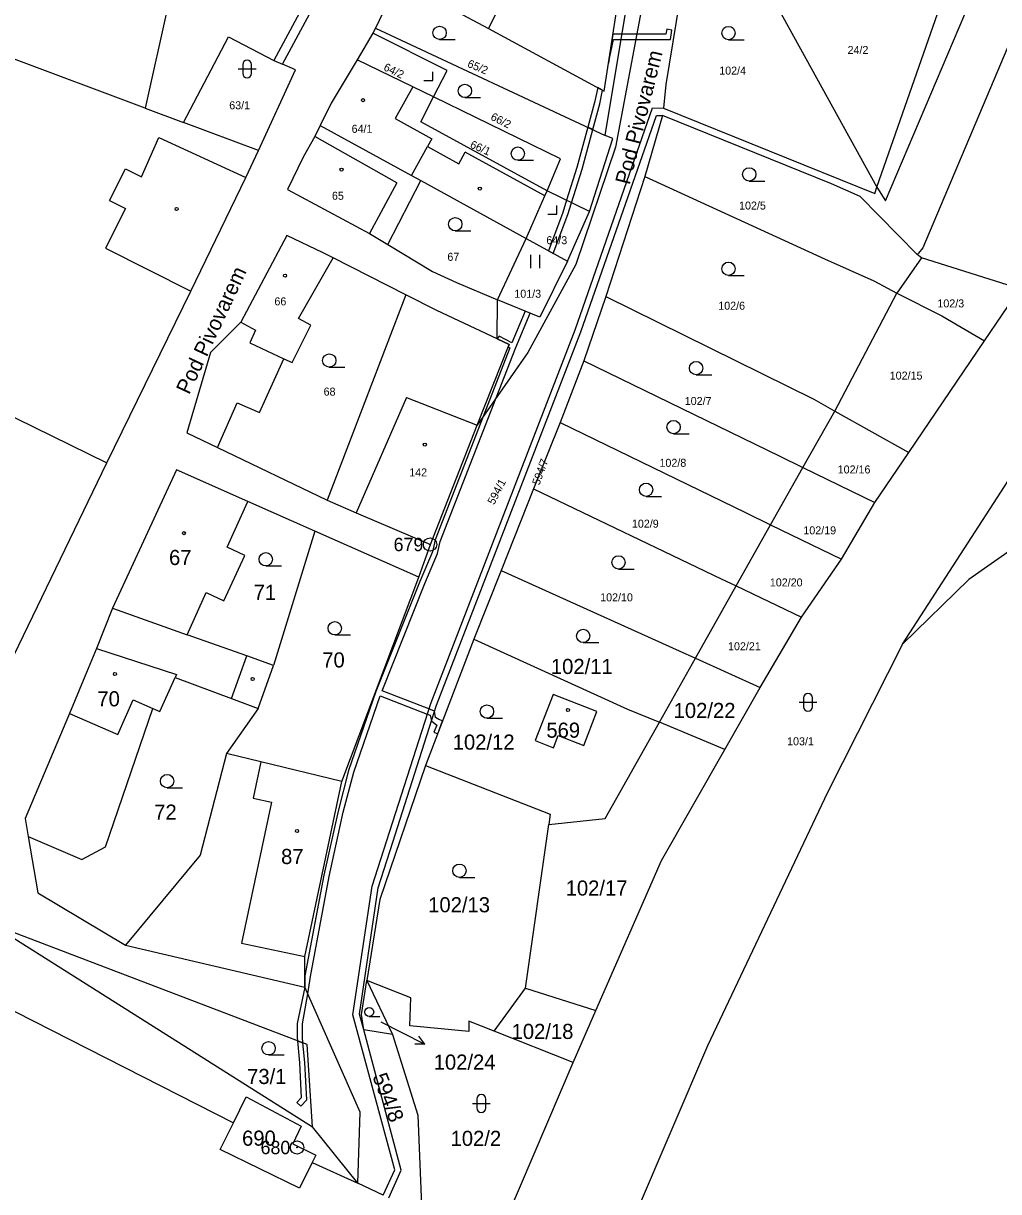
# Model space of a CAD drawing. Extents: x -758582 to -751794, y -998770 to -994350.
# Drawn here: x -755599.9 to -755490.3, y -995947.8 to -995816.3 of the extents above; entities that cross this region are included whole.
import ezdxf

# ---------------------------------------------------------------- set-up
doc = ezdxf.new("R2010")
doc.units = 0
for name, color, linetype in [('Hranice parcel', 7, 'Continuous'), ('Parcelní čísla', 7, 'Continuous'), ('Pop  PČ popisy', 7, 'Continuous'), ('Vnitřní kresba', 7, 'Continuous'), ('Věcná břemena k části', 7, 'Continuous'), ('Značky bodu BP', 7, 'Continuous'), ('Značky budov', 7, 'Continuous'), ('Značky kultur', 7, 'Continuous')]:
    doc.layers.add(name, color=color, linetype=linetype)

msp = doc.modelspace()

# ---------------------------------------------------------------- linework, layer by layer
at = {"layer": 'Hranice parcel'}
for p, q in [((-755520.42, -995804.92), (-755503.98, -995834.78)), ((-755557.34, -995810.55), (-755560.36, -995816.89)), ((-755551.75, -995814.75), (-755547.65, -995816.93)), ((-755560.66, -995817.44), (-755562.4, -995820.43)), ((-755560.36, -995816.89), (-755560.66, -995817.44)), ((-755560.36, -995816.89), (-755534.52, -995828.96)), ((-755571.79, -995820.54), (-755570.82, -995820.95)), ((-755586.26, -995825.88), (-755581.94, -995827.5)), ((-755528.07, -995826.7), (-755530.08, -995833.58)), ((-755529.19, -995825.85), (-755527.98, -995825.87)), ((-755528.77, -995826.71), (-755528.07, -995826.7)), ((-755573.52, -995830.66), (-755581.94, -995827.5)), ((-755558.98, -995841.21), (-755555.27, -995834.01)), ((-755555.27, -995834.01), (-755543.43, -995840.56)), ((-755530.08, -995833.58), (-755534.47, -995847.08)), ((-755536.3, -995837.52), (-755541.05, -995835.17)), ((-755538.76, -995843.08), (-755536.3, -995837.52)), ((-755546.64, -995847.43), (-755543.43, -995840.56)), ((-755543.43, -995840.56), (-755538.76, -995843.08)), ((-755499.31, -995842.18), (-755499.45, -995842.33)), ((-755498.96, -995842.74), (-755499.45, -995842.33)), ((-755556.96, -995846.87), (-755565.12, -995842.73)), ((-755498.96, -995842.74), (-755501.74, -995846.69)), ((-755487.9, -995846.2), (-755498.96, -995842.74)), ((-755491.86, -995852.05), (-755487.9, -995846.2)), ((-755556.96, -995846.87), (-755565.79, -995870)), ((-755546.68, -995851.83), (-755546.64, -995847.43)), ((-755534.47, -995847.08), (-755536.91, -995854.3)), ((-755534.47, -995847.08), (-755511.07, -995858.64)), ((-755508.72, -995859.96), (-755501.74, -995846.69)), ((-755569.72, -995854.51), (-755567.61, -995850.3)), ((-755500.39, -995864.64), (-755491.86, -995852.05)), ((-755536.91, -995854.3), (-755539.59, -995861.23)), ((-755536.91, -995854.3), (-755514.98, -995864.99)), ((-755511.07, -995858.64), (-755508.72, -995859.96)), ((-755512.29, -995866.3), (-755508.72, -995859.96)), ((-755508.72, -995859.96), (-755500.39, -995864.64)), ((-755554.16, -995874.97), (-755548.93, -995861.53)), ((-755539.59, -995861.23), (-755542.59, -995868.7)), ((-755539.59, -995861.23), (-755518.75, -995871.38)), ((-755578.13, -995864.06), (-755565.79, -995870)), ((-755514.98, -995864.99), (-755512.29, -995866.3)), ((-755504.19, -995870.25), (-755500.39, -995864.64)), ((-755515.92, -995872.76), (-755512.29, -995866.3)), ((-755512.29, -995866.3), (-755504.19, -995870.25)), ((-755542.59, -995868.7), (-755546.21, -995877.89)), ((-755542.59, -995868.7), (-755521.48, -995878.82)), ((-755567.18, -995873.47), (-755574.71, -995870.14)), ((-755507.96, -995876.63), (-755504.19, -995870.25)), ((-755518.75, -995871.38), (-755515.92, -995872.76)), ((-755519.79, -995879.63), (-755515.92, -995872.76)), ((-755515.92, -995872.76), (-755507.96, -995876.63)), ((-755567.18, -995873.47), (-755571.82, -995888.57)), ((-755555.47, -995878.66), (-755567.18, -995873.47)), ((-755555.47, -995878.66), (-755554.16, -995874.97)), ((-755512.46, -995883.14), (-755507.96, -995876.63)), ((-755546.21, -995877.89), (-755549.31, -995885.63)), ((-755546.21, -995877.89), (-755526.21, -995886.93)), ((-755564.14, -995901.65), (-755555.47, -995878.66)), ((-755521.48, -995878.82), (-755519.79, -995879.63)), ((-755524.37, -995887.76), (-755519.79, -995879.63)), ((-755519.79, -995879.63), (-755512.46, -995883.14)), ((-755517.1, -995891.05), (-755512.46, -995883.14)), ((-755549.31, -995885.63), (-755554.72, -995899.85)), ((-755549.31, -995885.63), (-755532.01, -995893.48)), ((-755591.72, -995886.67), (-755582.73, -995889.61)), ((-755526.21, -995886.93), (-755524.37, -995887.76)), ((-755573.55, -995893.44), (-755571.82, -995888.57)), ((-755528.42, -995894.96), (-755524.37, -995887.76)), ((-755524.37, -995887.76), (-755517.1, -995891.05)), ((-755584.59, -995893.75), (-755582.89, -995889.92)), ((-755582.73, -995889.61), (-755582.89, -995889.92)), ((-755521.08, -995898.04), (-755517.1, -995891.05)), ((-755573.55, -995893.44), (-755577.11, -995898.48)), ((-755532.01, -995893.48), (-755528.42, -995894.96)), ((-755521.08, -995898.04), (-755528.42, -995894.96)), ((-755554.72, -995899.85), (-755559.85, -995914.9)), ((-755554.72, -995899.85), (-755540.71, -995905.32)), ((-755540.71, -995905.32), (-755540.85, -995906.46)), ((-755543.5, -995924.88), (-755540.85, -995906.46)), ((-755559.85, -995914.9), (-755561.32, -995924.01)), ((-755603.54, -995917.67), (-755567.43, -995940.49)), ((-755588.45, -995920.03), (-755568.31, -995924.79)), ((-755561.32, -995924.01), (-755558.43, -995930.08)), ((-755547, -995929.71), (-755543.5, -995924.88)), ((-755543.5, -995924.88), (-755535.57, -995927.39)), ((-755561.67, -995929.57), (-755562.16, -995927.82)), ((-755538.13, -995933.24), (-755535.57, -995927.39)), ((-755558.43, -995930.08), (-755561.67, -995929.57)), ((-755538.13, -995933.24), (-755547, -995929.71)), ((-755547.06, -995954.19), (-755538.13, -995933.24)), ((-755562.35, -995946.84), (-755567.43, -995940.49)), ((-755567.49, -995944.51), (-755562.35, -995946.84)), ((-755559.5, -995948.19), (-755558.18, -995945.32)), ((-755559.5, -995948.19), (-755562.35, -995946.84))]:
    msp.add_line(p, q, dxfattribs=at)
for points in [[(-755489.32, -995719.48), (-755477.02, -995766.71), (-755484.53, -995807.78), (-755498.8, -995841.6), (-755499.31, -995842.18)], [(-755538.17, -995789.33), (-755529.99, -995802.59), (-755529.67, -995810.51), (-755533.37, -995830.29), (-755537.81, -995843.47), (-755543.24, -995853.38), (-755548.93, -995861.53)], [(-755570.82, -995820.95), (-755564.91, -995809.98), (-755557.18, -995795.28)], [(-755503.98, -995834.78), (-755493.46, -995804.64), (-755491.49, -995794.37)], [(-755503.98, -995834.78), (-755503.02, -995836.3), (-755490.26, -995806.26), (-755487.94, -995794.93)], [(-755582.21, -995803.41), (-755567.05, -995811.71), (-755571.79, -995820.54)], [(-755547.65, -995816.93), (-755542.35, -995806.35), (-755539.54, -995806.3)], [(-755523.79, -995806.25), (-755525, -995806.73), (-755527.7, -995823.23), (-755527.98, -995825.87)], [(-755584.98, -995808.56), (-755587.07, -995812.46), (-755583.66, -995814.26), (-755586.26, -995825.88)], [(-755547.65, -995816.93), (-755534.64, -995823.96), (-755532.34, -995809.15)], [(-755534.52, -995828.96), (-755531.3, -995809.54), (-755532.34, -995809.15)], [(-755553.82, -995824.62), (-755552.3, -995821.66), (-755560.66, -995817.44)], [(-755586.26, -995825.88), (-755601.67, -995820.12), (-755610.61, -995818.09)], [(-755581.94, -995827.5), (-755576.87, -995817.85), (-755571.79, -995820.54)], [(-755573.52, -995830.66), (-755569.34, -995821.56), (-755570.82, -995820.95)], [(-755562.4, -995820.43), (-755565.33, -995825.31), (-755566.57, -995827.82)], [(-755553.82, -995824.62), (-755556.15, -995823.48), (-755562.4, -995820.43)], [(-755541.05, -995835.17), (-755555.26, -995827.41), (-755553.82, -995824.62)], [(-755541.05, -995835.17), (-755539.55, -995831.6), (-755553.82, -995824.62)], [(-755558.18, -995945.32), (-755562.9, -995927.88), (-755560.74, -995913.41), (-755554.15, -995892.86), (-755537.92, -995850.84), (-755529.19, -995825.85)], [(-755562.16, -995927.82), (-755560.06, -995913.61), (-755558.4, -995908.45), (-755553.5, -995893.06), (-755537.27, -995851.05), (-755528.77, -995826.71)], [(-755499.45, -995842.33), (-755505.84, -995835.82), (-755509.06, -995834.39), (-755528.07, -995826.7)], [(-755527.98, -995825.87), (-755504.22, -995835.48), (-755503.98, -995834.78)], [(-755566.57, -995827.82), (-755567.19, -995829.08), (-755568.5, -995831.4), (-755570.25, -995835.02), (-755561.01, -995839.97), (-755558.98, -995841.21)], [(-755566.57, -995827.82), (-755556.29, -995833.45), (-755555.27, -995834.01)], [(-755536.3, -995837.52), (-755533.66, -995829.3), (-755534.52, -995828.96)], [(-755618.51, -995909.9), (-755611.25, -995908.1), (-755600.46, -995886.3), (-755590.57, -995865.79), (-755581.11, -995846.48), (-755574.92, -995833.7), (-755573.52, -995830.66)], [(-755530.08, -995833.58), (-755509.86, -995842.82), (-755504.3, -995845.3), (-755501.74, -995846.69)], [(-755543.43, -995840.56), (-755541.31, -995835.76), (-755541.05, -995835.17)], [(-755565.12, -995842.73), (-755566.22, -995842.16), (-755570.33, -995840.2), (-755575.51, -995849.96), (-755578.89, -995853.37), (-755581.56, -995862.41), (-755578.13, -995864.06)], [(-755558.98, -995841.21), (-755553.94, -995844.27), (-755551.24, -995845.51), (-755546.64, -995847.43)], [(-755567.61, -995850.3), (-755569.03, -995849.55), (-755565.12, -995842.73)], [(-755538.76, -995843.08), (-755541.89, -995849.4), (-755546.64, -995847.43)], [(-755546.68, -995851.83), (-755553.46, -995848.64), (-755556.96, -995846.87)], [(-755501.74, -995846.69), (-755496.68, -995849.23), (-755491.86, -995852.05)], [(-755501.09, -995886.17), (-755485.59, -995862.19), (-755476.21, -995849.9)], [(-755548.93, -995861.53), (-755545.32, -995852.47), (-755546.68, -995851.83)], [(-755472.53, -995851.07), (-755474.46, -995862.26), (-755475.15, -995865.92), (-755485.34, -995873.1), (-755493.64, -995878.9), (-755501.09, -995886.17)], [(-755578.13, -995864.06), (-755575.92, -995859.04), (-755573.4, -995860.13), (-755570.66, -995854.08), (-755569.72, -995854.51)], [(-755574.71, -995870.14), (-755582.72, -995866.59), (-755589.94, -995882.15), (-755591.72, -995886.67)], [(-755571.82, -995888.57), (-755574.84, -995887.51), (-755581.53, -995885.14), (-755579.39, -995880.37), (-755577.39, -995881.3), (-755575.04, -995876.22), (-755577.05, -995875.28), (-755574.71, -995870.14)], [(-755565.79, -995870), (-755562.53, -995871.42), (-755554.16, -995874.97)], [(-755591.72, -995886.67), (-755593.04, -995889.82), (-755594.78, -995893.97), (-755599.74, -995905.79), (-755599.4, -995907.81)], [(-755501.09, -995886.17), (-755509.51, -995902.87), (-755523.02, -995931.37), (-755531.04, -995950.11), (-755530.43, -995962.15)], [(-755582.89, -995889.92), (-755576.54, -995892.29), (-755573.55, -995893.44)], [(-755542.4, -995897.04), (-755540.34, -995897.84), (-755539.81, -995896.46), (-755536.94, -995897.57), (-755535.46, -995893.76), (-755540.39, -995891.85), (-755542.4, -995897.04)], [(-755599.4, -995907.81), (-755593.38, -995910.41), (-755590.71, -995908.98), (-755585.38, -995893.41), (-755584.59, -995893.75)], [(-755540.85, -995906.46), (-755534.52, -995905.8), (-755528.42, -995894.96)], [(-755577.11, -995898.48), (-755580.07, -995909.93), (-755588.45, -995920.03)], [(-755564.14, -995901.65), (-755573.25, -995899.42), (-755577.11, -995898.48)], [(-755535.57, -995927.39), (-755528.18, -995910.52), (-755521.08, -995898.04)], [(-755568.31, -995924.79), (-755568.31, -995921.34), (-755564.14, -995901.65)], [(-755599.4, -995907.81), (-755598.31, -995914.17), (-755588.45, -995920.03)], [(-755567.43, -995940.49), (-755568.03, -995931.24), (-755603.54, -995917.67)], [(-755615.6, -995919.2), (-755607.06, -995924.41), (-755576.33, -995940.02)], [(-755561.67, -995929.57), (-755561.94, -995927.83), (-755561.32, -995924.01)], [(-755547, -995929.71), (-755549.85, -995928.58), (-755549.87, -995929.77), (-755556.5, -995929.11), (-755556.38, -995925.98), (-755561.32, -995924.01)], [(-755562.35, -995946.84), (-755562.06, -995938.82), (-755568.31, -995924.79)], [(-755558.87, -995948.48), (-755557.45, -995945.37), (-755561.67, -995929.57)], [(-755558.43, -995930.08), (-755555.61, -995939.19), (-755555.16, -995950.24)], [(-755576.33, -995940.02), (-755574.91, -995937.11), (-755568.73, -995940.41), (-755569.65, -995942.41), (-755567.08, -995943.67), (-755567.49, -995944.51)], [(-755567.49, -995944.51), (-755568.9, -995947.39), (-755577.81, -995943.04), (-755576.33, -995940.02)]]:
    msp.add_lwpolyline(points, dxfattribs=at)
at = {"layer": 'Pop  PČ popisy'}
for p, q in [((-755559.74, -995928.67), (-755557.48, -995929.83)), ((-755557.48, -995929.83), (-755554.81, -995931.19)), ((-755554.81, -995931.19), (-755555.47, -995930.29)), ((-755554.81, -995931.19), (-755555.93, -995931.18))]:
    msp.add_line(p, q, dxfattribs=at)
at = {"layer": 'Vnitřní kresba'}
for p, q in [((-755556.15, -995823.48), (-755558.13, -995827.06)), ((-755558.13, -995827.06), (-755554.01, -995829.34)), ((-755586.67, -995833.6), (-755584.71, -995829.19)), ((-755584.71, -995829.19), (-755574.92, -995833.7)), ((-755557.96, -995834.29), (-755567.19, -995829.08)), ((-755554.01, -995829.34), (-755554.5, -995830.21)), ((-755556.29, -995833.45), (-755554.5, -995830.21)), ((-755554.5, -995830.21), (-755551, -995832.15)), ((-755551, -995832.15), (-755550.27, -995830.83)), ((-755541.31, -995835.76), (-755550.27, -995830.83)), ((-755590.26, -995836.27), (-755588.46, -995832.7)), ((-755588.46, -995832.7), (-755586.67, -995833.6)), ((-755557.96, -995834.29), (-755561.01, -995839.97)), ((-755588.47, -995837.17), (-755590.72, -995841.64)), ((-755590.26, -995836.27), (-755588.47, -995837.17)), ((-755590.72, -995841.64), (-755581.11, -995846.48)), ((-755575.51, -995849.96), (-755573.83, -995850.85)), ((-755573.83, -995850.85), (-755574.5, -995852.3)), ((-755574.5, -995852.3), (-755570.66, -995854.08)), ((-755609.7, -995856.42), (-755590.57, -995865.79)), ((-755556.87, -995858.43), (-755562.53, -995871.42)), ((-755556.87, -995858.43), (-755548.93, -995861.53)), ((-755589.94, -995882.15), (-755581.53, -995885.14)), ((-755576.54, -995892.29), (-755574.84, -995887.51)), ((-755589.31, -995896.34), (-755587.62, -995892.44)), ((-755587.62, -995892.44), (-755585.38, -995893.41)), ((-755594.78, -995893.97), (-755589.31, -995896.34)), ((-755573.25, -995899.42), (-755574.12, -995903.51)), ((-755572.05, -995903.95), (-755575.41, -995919.84)), ((-755574.12, -995903.51), (-755572.05, -995903.95)), ((-755575.41, -995919.84), (-755568.31, -995921.34))]:
    msp.add_line(p, q, dxfattribs=at)
at = {"layer": 'Věcná břemena k části'}
for points in [[(-755527.61, -995817.01), (-755527.7, -995817.57), (-755530.99, -995817.57), (-755532.63, -995817.56), (-755533.65, -995817.56), (-755534.16, -995820.84), (-755533.58, -995818.16), (-755532.73, -995818.16), (-755531.1, -995818.16), (-755527.18, -995818.17), (-755527.02, -995817.1)], [(-755535.36, -995823.57), (-755535.72, -995825.24), (-755536.48, -995828.04), (-755535.93, -995828.3), (-755535.14, -995825.38), (-755534.81, -995823.87)], [(-755540.36, -995842.22), (-755538.73, -995837.83), (-755538.32, -995836.52), (-755537.13, -995832.73), (-755535.93, -995828.3), (-755536.48, -995828.04), (-755537.71, -995832.57), (-755538.86, -995836.25), (-755539.29, -995837.63), (-755540.9, -995841.93)], [(-755542.97, -995848.95), (-755543.53, -995848.72), (-755545.02, -995852.28), (-755546.44, -995851.55), (-755546.68, -995851.83), (-755545.32, -995852.47), (-755545.43, -995852.74), (-755545.25, -995852.83), (-755548.25, -995860.56), (-755553.65, -995874.46), (-755553.95, -995875.81), (-755555.38, -995879.15), (-755560.32, -995891.51), (-755563.38, -995900.39), (-755564.57, -995904.96), (-755566.16, -995912.19), (-755568.31, -995923.48), (-755568.31, -995924.79), (-755569.15, -995928.85), (-755569.18, -995930.43), (-755569.14, -995930.81), (-755568.52, -995931.05), (-755568.58, -995930.41), (-755568.55, -995928.91), (-755567.98, -995925.53), (-755567.65, -995923.58), (-755565.58, -995912.31), (-755563.99, -995905.1), (-755562.8, -995900.57), (-755559.83, -995892.01), (-755554.53, -995894.05), (-755554.21, -995894.17), (-755554.06, -995894.82), (-755553.47, -995895.3), (-755553.78, -995896.1), (-755553.35, -995896.26), (-755552.81, -995894.82), (-755553.23, -995894.66), (-755553.6, -995894.42), (-755553.71, -995893.72), (-755554.35, -995893.47), (-755559.62, -995891.45), (-755554.82, -995879.37), (-755553.37, -995875.99), (-755553.07, -995874.64), (-755546.79, -995858.46), (-755544.59, -995852.8)], [(-755568.52, -995931.05), (-755569.14, -995930.81), (-755568.91, -995933.29), (-755568.71, -995937.24), (-755569.19, -995937.75), (-755568.76, -995938.16), (-755568.09, -995937.46), (-755568.31, -995933.25)]]:
    msp.add_lwpolyline(points, close=True, dxfattribs=at)
at = {"layer": 'Značky bodu BP'}
for centre, radius in [((-755554.22, -995874.97), 0.75), ((-755554.22, -995874.97), 0.03), ((-755569.18, -995942.81), 0.75), ((-755569.18, -995942.81), 0.03)]:
    msp.add_circle(centre, radius, dxfattribs=at)
at = {"layer": 'Značky budov'}
for centre in [(-755561.77, -995824.98), (-755564.18, -995832.8), (-755548.62, -995834.94), (-755582.72, -995837.23), (-755570.53, -995844.73), (-755554.8, -995863.73), (-755581.9, -995873.7), (-755589.65, -995889.55), (-755574.17, -995890.1), (-755538.71, -995893.59), (-755569.18, -995907.21)]:
    msp.add_circle(centre, 0.175, dxfattribs=at)
at = {"layer": 'Značky kultur'}
for p, q in [((-755553.14, -995818.16), (-755551.39, -995818.16)), ((-755520.66, -995818.18), (-755518.91, -995818.18)), ((-755575.79, -995821.47), (-755573.79, -995821.47)), ((-755575.29, -995820.97), (-755575.29, -995821.97)), ((-755574.29, -995821.97), (-755574.29, -995820.97)), ((-755554.92, -995822.78), (-755553.92, -995822.78)), ((-755553.92, -995822.78), (-755553.92, -995821.78)), ((-755550.3, -995824.69), (-755548.55, -995824.69)), ((-755544.35, -995831.75), (-755542.6, -995831.75)), ((-755518.33, -995834.08), (-755516.58, -995834.08)), ((-755539.96, -995837.82), (-755539.96, -995836.82)), ((-755540.96, -995837.82), (-755539.96, -995837.82)), ((-755551.38, -995839.69), (-755549.63, -995839.69)), ((-755542.87, -995843.87), (-755542.87, -995842.37)), ((-755541.87, -995843.87), (-755541.87, -995842.37)), ((-755520.66, -995844.7), (-755518.91, -995844.7)), ((-755565.55, -995855.02), (-755563.8, -995855.02)), ((-755524.3, -995855.88), (-755522.55, -995855.88)), ((-755526.84, -995862.51), (-755525.09, -995862.51)), ((-755529.93, -995869.56), (-755528.18, -995869.56)), ((-755572.69, -995877.39), (-755570.94, -995877.39)), ((-755533.03, -995877.73), (-755531.28, -995877.73)), ((-755564.93, -995885.15), (-755563.18, -995885.15)), ((-755537, -995886.01), (-755535.25, -995886.01)), ((-755512.22, -995892.22), (-755512.22, -995893.22)), ((-755511.22, -995893.22), (-755511.22, -995892.22)), ((-755512.72, -995892.72), (-755510.72, -995892.72)), ((-755547.82, -995894.52), (-755546.07, -995894.52)), ((-755583.79, -995902.34), (-755582.04, -995902.34)), ((-755550.92, -995912.42), (-755549.17, -995912.42)), ((-755561.06, -995928.06), (-755559.88, -995928.06)), ((-755572.37, -995932.4), (-755570.62, -995932.4)), ((-755549.46, -995937.86), (-755547.46, -995937.86)), ((-755548.96, -995937.36), (-755548.96, -995938.36)), ((-755547.96, -995938.36), (-755547.96, -995937.36))]:
    msp.add_line(p, q, dxfattribs=at)
for centre, radius in [((-755553.14, -995817.41), 0.75), ((-755520.66, -995817.43), 0.75), ((-755550.3, -995823.94), 0.75), ((-755544.35, -995831), 0.75), ((-755518.33, -995833.33), 0.75), ((-755551.38, -995838.94), 0.75), ((-755520.66, -995843.95), 0.75), ((-755565.55, -995854.27), 0.75), ((-755524.3, -995855.13), 0.75), ((-755526.84, -995861.76), 0.75), ((-755529.93, -995868.81), 0.75), ((-755572.69, -995876.64), 0.75), ((-755533.03, -995876.98), 0.75), ((-755564.93, -995884.4), 0.75), ((-755537, -995885.26), 0.75), ((-755547.82, -995893.77), 0.75), ((-755583.79, -995901.59), 0.75), ((-755550.92, -995911.67), 0.75), ((-755561.06, -995927.56), 0.502), ((-755572.37, -995931.65), 0.75)]:
    msp.add_circle(centre, radius, dxfattribs=at)
for centre, start, end in [((-755574.79, -995820.97), 0, 180), ((-755574.79, -995821.97), 180, 359.9879), ((-755511.72, -995892.22), 0, 180), ((-755511.72, -995893.22), 180, 359.9879), ((-755548.46, -995937.36), 0, 180), ((-755548.46, -995938.36), 180, 359.9879)]:
    msp.add_arc(centre, 0.5, start, end, dxfattribs=at)

# ---------------------------------------------------------------- texts
at = {"layer": 'Parcelní čísla'}
for s, height, p in [('24/2', 0.9, (-755507.27, -995819.79)), ('102/4', 0.9, (-755521.7, -995822.11)), ('63/1', 0.9, (-755576.8, -995826.01)), ('64/1', 0.9, (-755563.04, -995828.66)), ('65', 0.9, (-755565.25, -995836.19)), ('102/5', 0.9, (-755519.47, -995837.29)), ('64/3', 0.9, (-755541.14, -995841.19)), ('67', 0.9, (-755552.27, -995843.06)), ('101/3', 0.9, (-755544.74, -995847.21)), ('66', 0.9, (-755571.72, -995848.07)), ('102/6', 0.9, (-755521.81, -995848.56)), ('102/3', 0.9, (-755497.17, -995848.3)), ('102/15', 0.9, (-755502.53, -995856.42)), ('68', 0.9, (-755566.19, -995858.22)), ('102/7', 0.9, (-755525.58, -995859.28)), ('102/8', 0.9, (-755528.42, -995866.23)), ('102/16', 0.9, (-755508.38, -995866.98)), ('142', 0.9, (-755556.56, -995867.31)), ('102/9', 0.9, (-755531.52, -995873.08)), ('102/19', 0.9, (-755512.24, -995873.83)), ('67', 1.7, (-755583.57, -995877.28)), ('71', 1.7, (-755574.06, -995881.2)), ('102/20', 0.9, (-755516.01, -995879.69)), ('102/10', 0.9, (-755535.09, -995881.37)), ('102/21', 0.9, (-755520.71, -995886.87)), ('70', 1.7, (-755566.34, -995888.81)), ('102/11', 1.7, (-755540.63, -995889.54)), ('70', 1.7, (-755591.63, -995893.18)), ('102/22', 1.7, (-755526.83, -995894.49)), ('569', 1.7, (-755541.14, -995896.71)), ('102/12', 1.7, (-755551.67, -995898.05)), ('103/1', 0.9, (-755514.07, -995897.56)), ('72', 1.7, (-755585.24, -995905.93)), ('87', 1.7, (-755570.97, -995910.92)), ('102/17', 1.7, (-755538.97, -995914.47)), ('102/13', 1.7, (-755554.43, -995916.35)), ('102/18', 1.7, (-755545.05, -995930.6)), ('102/24', 1.7, (-755553.81, -995934.05)), ('73/1', 1.7, (-755574.79, -995935.67)), ('690', 1.7, (-755575.36, -995942.61)), ('102/2', 1.7, (-755551.91, -995942.63))]:
    msp.add_text(s, height=height, dxfattribs=at).set_placement(p)
for s, height, rotation, p in [('64/2', 0.9, 334, (-755559.53, -995821.57)), ('65/2', 0.9, 337, (-755550.1, -995821.2)), ('66/2', 0.9, 333, (-755547.49, -995827.14)), ('66/1', 0.9, 336, (-755549.8, -995830.29)), ('594/7', 0.9, 70, (-755541.93, -995868.37)), ('594/1', 0.9, 63, (-755547.01, -995870.57)), ('594/8', 1.7, 291, (-755560.73, -995934.82))]:
    msp.add_text(s, height=height, rotation=rotation, dxfattribs=at).set_placement(p)
at = {"layer": 'Pop  PČ popisy'}
for rotation, p in [(76, (-755531.78, -995834.58)), (65, (-755581.31, -995858.19))]:
    msp.add_text('Pod Pivovarem', height=1.7, rotation=rotation, dxfattribs=at).set_placement(p)
at = {"layer": 'Značky bodu BP'}
for s, p in [('679', (-755558.32, -995875.72)), ('680', (-755573.28, -995943.56))]:
    msp.add_text(s, height=1.5, dxfattribs=at).set_placement(p)

doc.saveas('drawing.dxf')
